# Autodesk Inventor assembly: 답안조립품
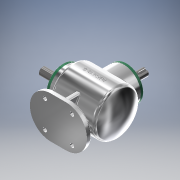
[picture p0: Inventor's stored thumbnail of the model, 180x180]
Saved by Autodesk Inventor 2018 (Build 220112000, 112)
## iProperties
Created: 2023-01
Part Number: 답안조립품
Material: 일반
Document SubType Name: Assembly
Designer: home
Author: home
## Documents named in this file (14)
- C:\Users\home\Desktop\730106V1010\답안조립품.iam
- C:\Users\home\Desktop\730106V1010\본체.ipt
- C:\Users\home\Desktop\730106V1010\메인 축.ipt
- 메인 축.ipt
- C:\Users\home\Desktop\730106V1010\베어링 6203.ipt
- C:\Users\home\Desktop\730106V1010\커버.ipt
- C:\Users\home\Desktop\730106V1010\오일실 17 32 8.ipt
- C:\Users\home\Desktop\730106V1010\메인 베벨기어.ipt
- C:\Users\home\Desktop\730106V1010\키 5x5.ipt
- C:\Users\home\Desktop\730106V1010\M4.ipt
- C:\Users\home\Desktop\730106V1010\서브 축.ipt
- 서브 축.ipt
- C:\Users\home\Desktop\730106V1010\키 4x4.ipt
- C:\Users\home\Desktop\730106V1010\서브 베벨기어.ipt
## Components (8 placed, 1 different names)
1. M4:1
2. M4:2
3. M4:3
4. M4:4
5. M4:5
6. M4:6
7. M4:7
8. M4:8
